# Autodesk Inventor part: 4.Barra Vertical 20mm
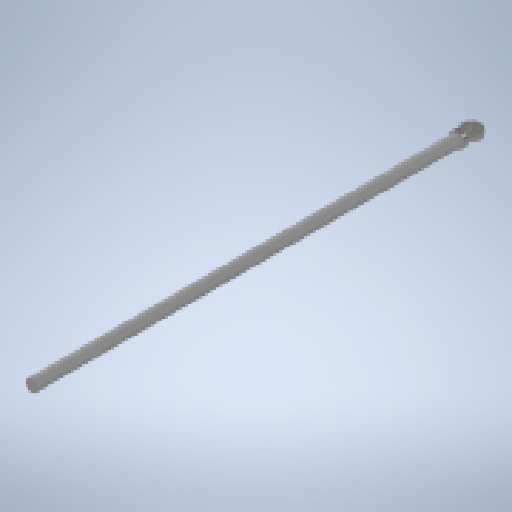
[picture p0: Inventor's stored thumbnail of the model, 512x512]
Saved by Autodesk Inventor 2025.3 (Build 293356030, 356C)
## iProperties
Created: 2025-10
Part Number: 4.Barra Vertical 20mm
Material: Genérico
Document SubType Name: Modeling
Designer: User
Density: 1 g/cm^3
Appearance: Valor por defecto
Author: User
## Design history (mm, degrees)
sketch "Boceto1"
  geometry: C1 r 10 at (0, 0); 1 further point
  constraints: 1 centre point
  dimensions: "d0" = 0 distance of point (0, 0) C1.centre; "d1" = 0 distance of point (0, 0) C1.centre; "d2" = 20 diameter of C1
extrude "Extrusión1" new body sketch "Boceto1" distance "d3" = 500; taper "d4" = 0 deg
node "Plano de trabajo1"
sketch "Boceto4"
  geometry: C1 r 10 at (0, 0) reference; C2 r 12.5 at (0, 0); 1 further point
  constraints: 1 centre point
  dimensions: "d6" = 0 distance of point (0, 0) C2.centre; "d7" = 0 distance of C2.centre point (0, 0); "d8" = 25 diameter of C2
extrude "Extrusión2" join sketch "Boceto4" distance "d9" = 10; taper "d10" = 0 deg
sketch "Boceto5"
  geometry: L1 (-12.5, -10)-(12.5, -10) reference; L2 (-12.5, 0)-(-12.5, -10) reference; C1 r 15 at (0, -25); 2 further points
  constraints: 1 centre point, 1 midpoint
  dimensions: "d11" = 15 distance from line of C1.centre L1; "d13" = 30 diameter of C1; "d14" = 0 horizontal distance of C1.centre point (0, -10)
extrude "Extrusión3" join sketch "Boceto5" stored distance "d15" = 10; taper "d16" = 0 deg
sketch "Boceto6"
  geometry: 4 further points
  constraints: 1 vertical alignment
  dimensions: "d17" = 0 distance of point (0, 0) point (0, 0); "d18" = 0 distance of point (0, 0) point (0, 0)
hole "Agujero1" sketch "Boceto6" at (0, 0) diameter "d19" = 10.106; stored, may be unused: countersink angle "d23" = 90 deg, drill point angle "d25" = 118 deg; dims "d20" = 24, "d21" = 4, "d22" = 2, "d24" = 8
feature "Rosca1" dims "d26" = 500, "d27" = 0
node "Sólido1"
node "Acabados"
node "Finish1" dims "Finish1_Area" = 428.04023
